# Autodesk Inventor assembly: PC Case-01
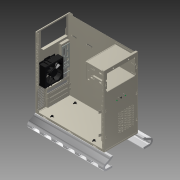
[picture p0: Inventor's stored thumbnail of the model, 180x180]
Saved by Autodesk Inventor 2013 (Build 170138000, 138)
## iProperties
Company: Autodesk Inc.
Created: 2006-09
Part Number: PC Case-01
Document SubType Name: Assembly
Designer: Autodesk Inc.
Mass: 1117.78 g
Surface Area: 13233.4 cm^2
Volume: 1117.78 cm^3
Density: 1 g/cm^3
Author: Autodesk Inc.
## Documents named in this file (16)
- Z:\_DATEN\Personal Computer\PC Chassis\PC Chassis.iam
- Z:\_DATEN\Personal Computer\PC Chassis\Bottom Bracket.ipt
- Z:\_DATEN\Personal Computer\PC Chassis\Back Bracket.ipt
- Z:\_DATEN\Personal Computer\PC Chassis\Front Bracket.ipt
- Z:\_DATEN\Personal Computer\PC Chassis\Graphic Card Cover.ipt
- Z:\_DATEN\Personal Computer\PC Chassis\Graphic Card Support.ipt
- Z:\_DATEN\Personal Computer\PC Chassis\Module Protector.ipt
- Z:\_DATEN\Personal Computer\PC Chassis\Blank Insert.ipt
- Z:\_DATEN\Personal Computer\PC Chassis\Bottom Casing Stopper.ipt
- Z:\_DATEN\Personal Computer\PC Chassis\CDROM Bracket 01.ipt
- Z:\_DATEN\Personal Computer\PC Chassis\CDROM Bracket 02.ipt
- Z:\_DATEN\Personal Computer\PC Chassis\Hard Drive Bracket.ipt
- Z:\_DATEN\Personal Computer\PC Chassis\Motherboard Support.ipt
- Z:\_DATEN\Personal Computer\PC Chassis\Bottom Plastic.ipt
- Z:\_DATEN\Personal Computer\PC Chassis\Cooling Fan.ipt
- Z:\_DATEN\Personal Computer\PC Chassis\Power Module.ipt
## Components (20 placed, 15 different names)
1. Bottom Bracket:1 — Mate:2, Mate:8, Mate:25, Mate:26, Angle:1, Mate:27, Mate:28, Angle:2, Mate:29, Mate:30, Angle:3, Mate:31, Mate:32, Angle:4, Mate:37, Mate:49, Mate:52, Mate:56
2. Front Bracket:2 — Mate:2, Mate:4, Mate:5, Mate:39, Mate:41, Flush:5, Mate:42, Flush:6, Mate:56
3. Back Bracket:1 — Mate:8, Mate:11, Mate:13, Mate:14, Mate:44, Mate:45, Mate:46
4. Graphic Card Cover:1 — Mate:11, Mate:13, Mate:14, Mate:15, Mate:16, Mate:17, Mate:53, Mate:54, Mate:55
5. Graphic Card Support:1 — Mate:15, Mate:16, Mate:17, Mate:19, Mate:20, Mate:22, Mate:23
6. Module Protector:1 — Mate:53, Mate:54, Mate:55
7. Blank Insert:1 — Mate:19, Mate:20
8. Blank Insert:2 — Mate:22, Mate:23
9. Bottom Casing Stopper:1 — Mate:25, Mate:26, Angle:1, Flush:1, Mate:35
10. Bottom Casing Stopper:2 — Mate:29, Mate:30, Angle:3, Flush:2, Mate:36
11. Bottom Casing Stopper:3 — Mate:31, Mate:32, Angle:4, Flush:4, Mate:33
12. Bottom Casing Stopper:4 — Mate:27, Mate:28, Angle:2, Flush:3, Mate:34
13. CDROM Bracket 01:2 — Mate:42, Mate:43, Flush:6
14. CDROM Bracket 02:1 — Mate:40, Mate:41, Flush:5
15. Cooling Fan:2 — Mate:44, Mate:45, Mate:46
16. Hard Drive Bracket:1 — Mate:50, Mate:51, Mate:52
17. Hard Drive Bracket:2 — Mate:48, Mate:49, Mate:51
18. Power Module:1 — Mate:4, Mate:5
19. Motherboard Support:1 — Mate:37, Mate:39, Mate:40, Mate:43, Mate:48, Mate:50
20. Bottom Plastic:1 — Flush:1, Flush:2, Flush:3, Flush:4, Mate:33, Mate:34, Mate:35, Mate:36
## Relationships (54: Mate 44, Flush 6, Angle 4)
- Mate:2: Bottom Bracket:1 ↔ Front Bracket:2
- Mate:4: Front Bracket:2 ↔ Power Module:1
- Mate:5: Front Bracket:2 ↔ Power Module:1
- Mate:8: Bottom Bracket:1 ↔ Back Bracket:1
- Mate:11: Back Bracket:1 ↔ Graphic Card Cover:1
- Mate:13: Back Bracket:1 ↔ Graphic Card Cover:1
- Mate:14: Back Bracket:1 ↔ Graphic Card Cover:1
- Mate:15: Graphic Card Cover:1 ↔ Graphic Card Support:1
- Mate:16: Graphic Card Cover:1 ↔ Graphic Card Support:1
- Mate:17: Graphic Card Cover:1 ↔ Graphic Card Support:1
- Mate:19: Graphic Card Support:1 ↔ Blank Insert:1
- Mate:20: Graphic Card Support:1 ↔ Blank Insert:1
- Mate:22: Graphic Card Support:1 ↔ Blank Insert:2
- Mate:23: Graphic Card Support:1 ↔ Blank Insert:2
- Mate:25: Bottom Bracket:1 ↔ Bottom Casing Stopper:1
- Mate:26: Bottom Bracket:1 ↔ Bottom Casing Stopper:1
- Angle:1: Bottom Bracket:1 ↔ Bottom Casing Stopper:1
- Mate:27: Bottom Bracket:1 ↔ Bottom Casing Stopper:4
- Mate:28: Bottom Bracket:1 ↔ Bottom Casing Stopper:4
- Angle:2: Bottom Bracket:1 ↔ Bottom Casing Stopper:4
- Mate:29: Bottom Bracket:1 ↔ Bottom Casing Stopper:2
- Mate:30: Bottom Bracket:1 ↔ Bottom Casing Stopper:2
- Angle:3: Bottom Bracket:1 ↔ Bottom Casing Stopper:2
- Mate:31: Bottom Bracket:1 ↔ Bottom Casing Stopper:3
- Mate:32: Bottom Bracket:1 ↔ Bottom Casing Stopper:3
- Angle:4: Bottom Bracket:1 ↔ Bottom Casing Stopper:3
- Flush:1: Bottom Casing Stopper:1 ↔ Bottom Plastic:1
- Flush:2: Bottom Casing Stopper:2 ↔ Bottom Plastic:1
- Flush:3: Bottom Casing Stopper:4 ↔ Bottom Plastic:1
- Flush:4: Bottom Casing Stopper:3 ↔ Bottom Plastic:1
- Mate:33: Bottom Casing Stopper:3 ↔ Bottom Plastic:1
- Mate:34: Bottom Casing Stopper:4 ↔ Bottom Plastic:1
- Mate:35: Bottom Casing Stopper:1 ↔ Bottom Plastic:1
- Mate:36: Bottom Casing Stopper:2 ↔ Bottom Plastic:1
- Mate:37: Bottom Bracket:1 ↔ Motherboard Support:1
- Mate:39: Front Bracket:2 ↔ Motherboard Support:1
- Mate:40: CDROM Bracket 02:1 ↔ Motherboard Support:1
- Mate:41: Front Bracket:2 ↔ CDROM Bracket 02:1
- Flush:5: Front Bracket:2 ↔ CDROM Bracket 02:1
- Mate:42: Front Bracket:2 ↔ CDROM Bracket 01:2
- Mate:43: CDROM Bracket 01:2 ↔ Motherboard Support:1
- Flush:6: Front Bracket:2 ↔ CDROM Bracket 01:2
- Mate:44: Back Bracket:1 ↔ Cooling Fan:2
- Mate:45: Back Bracket:1 ↔ Cooling Fan:2
- Mate:46: Back Bracket:1 ↔ Cooling Fan:2
- Mate:48: Hard Drive Bracket:2 ↔ Motherboard Support:1
- Mate:49: Bottom Bracket:1 ↔ Hard Drive Bracket:2
- Mate:50: Hard Drive Bracket:1 ↔ Motherboard Support:1
- Mate:51: Hard Drive Bracket:1 ↔ Hard Drive Bracket:2
- Mate:52: Bottom Bracket:1 ↔ Hard Drive Bracket:1
- Mate:53: Graphic Card Cover:1 ↔ Module Protector:1
- Mate:54: Graphic Card Cover:1 ↔ Module Protector:1
- Mate:55: Graphic Card Cover:1 ↔ Module Protector:1
- Mate:56: Bottom Bracket:1 ↔ Front Bracket:2
